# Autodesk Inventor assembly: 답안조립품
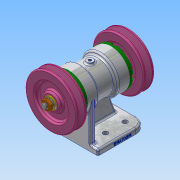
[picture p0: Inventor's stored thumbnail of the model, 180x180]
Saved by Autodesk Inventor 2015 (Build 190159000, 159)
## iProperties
Created: 2020-06
Part Number: 답안조립품
Document SubType Name: Assembly
Designer: user
Author: user
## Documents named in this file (11)
- C:\Users\user\Desktop\700606V1039\답안조립품.iam
- C:\Users\user\Desktop\700606V1039\본체.ipt
- C:\Users\user\Desktop\700606V1039\축.ipt
- C:\Users\user\Desktop\700606V1039\베어링 6204.ipt
- C:\Users\user\Desktop\700606V1039\오일 실 20 32 5.ipt
- C:\Users\user\Desktop\700606V1039\커버.ipt
- C:\Users\user\Desktop\700606V1039\키 5x5x12.ipt
- C:\Users\user\Desktop\700606V1039\V-벨트풀리.ipt
- C:\Users\user\Desktop\700606V1039\너트 M10.ipt
- C:\Users\user\Desktop\700606V1039\스프링 와셔 10.ipt
- C:\Users\user\Desktop\700606V1039\평면 와셔 10x21.ipt
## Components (2 placed, 1 different names)
1. V-벨트풀리:1
2. V-벨트풀리:2
## Named parameters: d3_d2 = 0
